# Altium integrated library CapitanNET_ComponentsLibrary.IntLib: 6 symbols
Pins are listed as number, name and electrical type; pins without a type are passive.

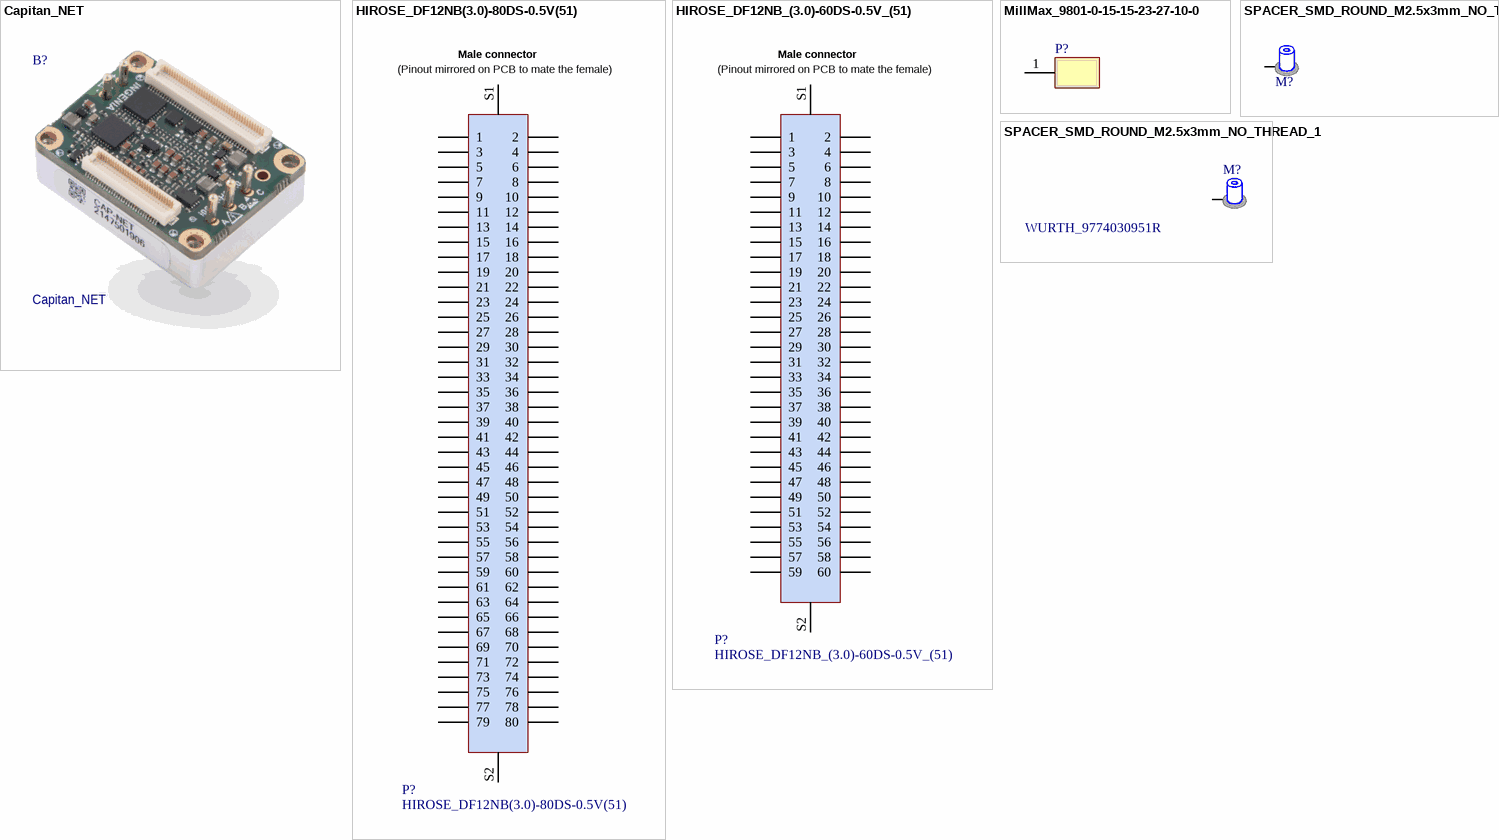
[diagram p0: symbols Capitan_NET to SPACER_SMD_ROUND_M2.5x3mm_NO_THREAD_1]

## Capitan_NET
designator B?
Capitan NET high-performance Servo Drive from Ingenia Motion Control.; ManufacturerPN: CAP-NET-E; IsPreferred: 0; IngeniaID: 5083; TemperatureMaxC: 85; TemperatureMinC: -40; MTBF55h: 600000; AlternativePN: CAP-NET-C
footprint CAPITAN_NET

## HIROSE_DF12NB(3.0)-80DS-0.5V(51)
designator P?
Connector SMD Mezzanine, 80 ways, 0.5mm pitch, 3mm stack height. Male with metal fitting; ManufacturerName: Hirose; IsPreferred: 0; IngeniaID: 5173; TemperatureMaxC: 125; TemperatureMinC: -45; MTBF55h: 176336644; AlternativePN: DF12(3.0)-80DS-0.5V(86)
footprint HIROSE_DF12NB(3.0)-80DS-0.5V(51)
footprint HIROSE_DF12NB(3.0)-80DS-0.5V(51)_ROTATED
pins: 1, 2, 3, 4, 5, 6, 7, 8, 9, 10, 11, 12, 13, 14, 15, 16, 17, 18, 19, 20, 21, 22, 23, 24, 25, 26, 27, 28, 29, 30, 31, 32, 33, 34, 35, 36, 37, 38, 39, 40, 41, 42, 43, 44, 45, 46, 47, 48, 49, 50, 51, 52, 53, 54, 55, 56, 57, 58, 59, 60, 61, 62, 63, 64, 65, 66, 67, 68, 69, 70, 71, 72, 73, 74, 75, 76, 77, 78, 79, 80, S1 Shield2, S2 Shield2

## HIROSE_DF12NB_(3.0)-60DS-0.5V_(51)
designator P?
Connector SMD Mezzanine, Black 60 ways, 0.5mm pitch, 3mm stack height. Male; ManufacturerName: Hirose; ManufacturerPN: DF12NB(3.0)-60DS-0.5V(51); IsPreferred: 0; IngeniaID: 5203; TemperatureMaxC: 125; TemperatureMinC: -55
footprint HIROSE_DF12NB(3.0)-60DS-0.5V(51)
footprint HIROSE_DF12NB(3.0)-60DS-0.5V(51)_ROTATED
pins: 1, 2, 3, 4, 5, 6, 7, 8, 9, 10, 11, 12, 13, 14, 15, 16, 17, 18, 19, 20, 21, 22, 23, 24, 25, 26, 27, 28, 29, 30, 31, 32, 33, 34, 35, 36, 37, 38, 39, 40, 41, 42, 43, 44, 45, 46, 47, 48, 49, 50, 51, 52, 53, 54, 55, 56, 57, 58, 59, 60, S1 shield1, S2 Shield2

## MillMax_9801-0-15-15-23-27-10-0
designator P?
1pin, receptacle for MillMax 6142, blind end; ManufacturerPN: 9801-0-15-15-23-27-10-0; CompletePN: MillMax_9801-0-15-15-23-27-10-0; IsPreferred: 0; IngeniaID: 4685; TemperatureMaxC: 125; TemperatureMinC: -55
footprint MillMax_9801-0-15-15-23-27-10-0
pins: 1

## SPACER_SMD_ROUND_M2.5x3mm_NO_THREAD
designator M?
Round SMD standoff M2.5 3mm height No Threaded Steel; ManufacturerName: Wurth Electronics Inc; ManufacturerPN: 9774030951R; CompletePN: SPACER_SMD_ROUND_M2.5x3mm_NO_THREAD; IsPreferred: 0; IngeniaID: 4248; TemperatureMaxC: 200; TemperatureMinC: -40
footprint WURTH_9774030951R
footprint WURTH_9774030951R_small
pins: 1 (power) "Positive supply"

## SPACER_SMD_ROUND_M2.5x3mm_NO_THREAD_1
designator M?, comment WURTH_9774030951R
Round SMD standoff M2.5 3mm height No Threaded Steel; ManufacturerName: Wurth Electronics Inc; CompletePN: SPACER_SMD_ROUND_M2.5x3mm_NO_THREAD; IsPreferred: 0; IngeniaID: 4248; TemperatureMaxC: 200; TemperatureMinC: -40
footprint WURTH_9774030951R
footprint WURTH_9774030951R_small
pins: 1 (power) "Positive supply"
